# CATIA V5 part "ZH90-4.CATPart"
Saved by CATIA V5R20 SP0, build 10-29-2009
Part number: ZH904
Bounding box of the stored display mesh (mm): x 0 to 359, y -20 to 55, z -29.7 to 15
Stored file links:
  C:\Users\Utente\Desktop\IO LAVORO\3D X SITO CF\X SITO\PLASTICA\ZH90\ZH90-4.CATPart
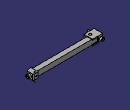
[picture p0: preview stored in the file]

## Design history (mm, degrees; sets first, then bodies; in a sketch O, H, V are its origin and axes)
Set1
  DatumSurface1 to DatumSurface16 "_ZH90/4_head"
  DatumSurface17 to DatumSurface34 "_ZH90/4_screw1"
  DatumSurface35 to DatumSurface55 "_ZH90/4_hand"
  DatumSurface56 to DatumSurface73 "_ZH90/4_screw2"
  DatumSurface74 to DatumSurface94 "_ZH90/4_he"
  DatumSurface95 to DatumSurface109 "_ZH90/4_screw3"
  DatumSurface110 to DatumSurface117 "_ZH90/4_stift1"
  DatumSurface118 to DatumSurface127 "_ZH90/4_stift2"
Body1 (main body)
